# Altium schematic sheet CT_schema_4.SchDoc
size 284 x 147 mm
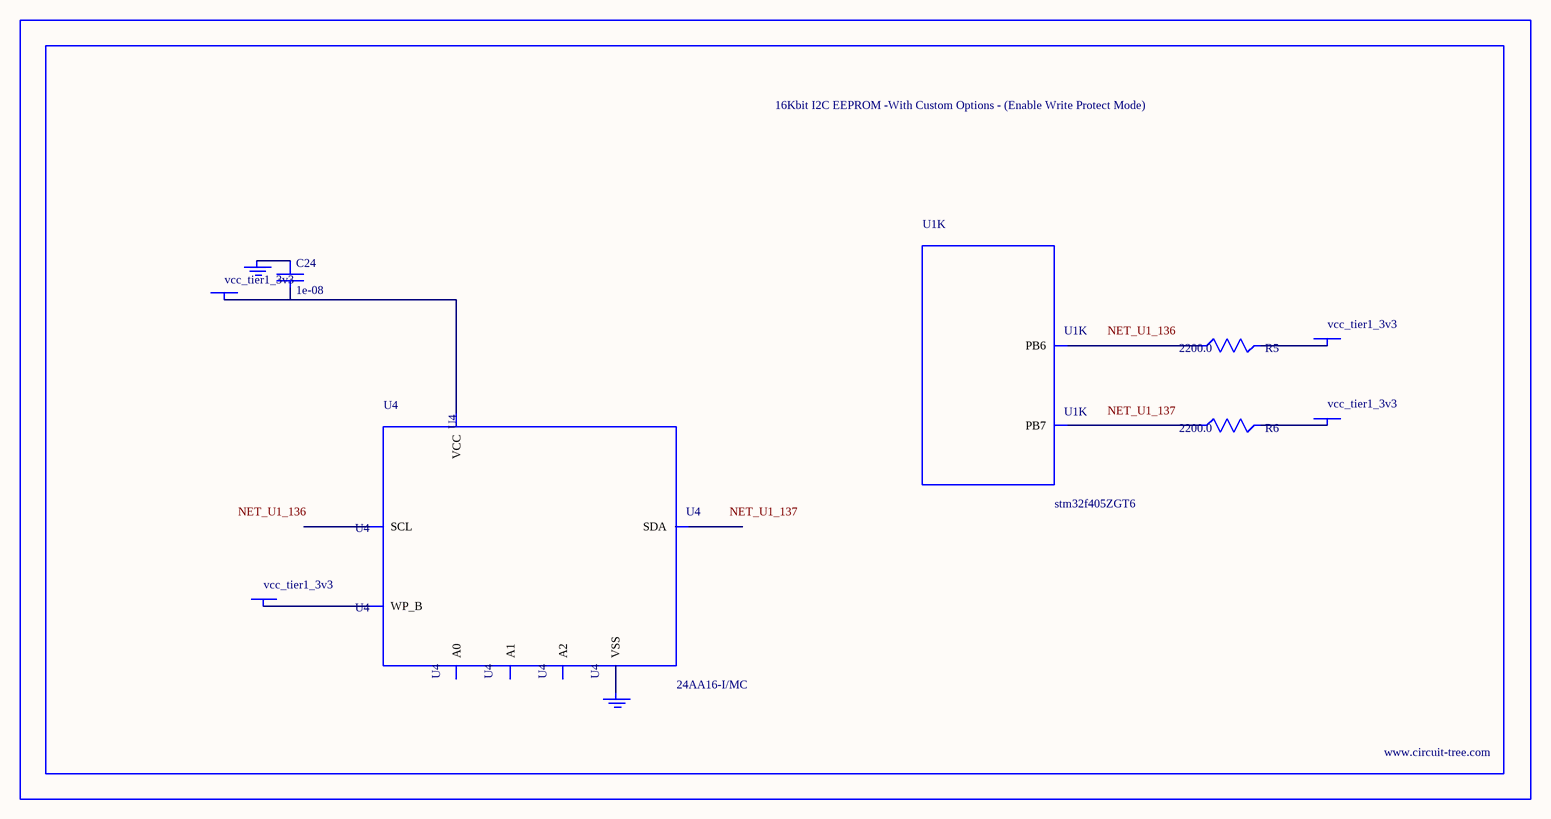
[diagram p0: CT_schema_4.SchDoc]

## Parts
BORDER3  (no value)
C24  1e-08  [C0402]
GND_INSTANCE_3_0  (no value)
GND_INSTANCE_3_1  (no value)
POWER_INSTANCE_3_0  vcc_tier1_3v3
POWER_INSTANCE_3_1  vcc_tier1_3v3
POWER_INSTANCE_3_2  vcc_tier1_3v3
POWER_INSTANCE_3_3  vcc_tier1_3v3
R5  2200.0  [R0603]
R6  2200.0  [R0603]
U1  stm32f405ZGT6  [LQFP144]  (part K of 13)
U4  24AA16-I/MC  [TDFN-8/6MM]

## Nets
NetC24_1: C24.1 GND_INSTANCE_3_0.0(GND)
NetC24_2: C24.2 POWER_INSTANCE_3_1.0(PWR) U4.8(VCC)
NetGND_INSTANCE_3_1_0: GND_INSTANCE_3_1.0(GND) U4.4(VSS)
NetPOWER_INSTANCE_3_0_0: POWER_INSTANCE_3_0.0(PWR) U4.7(WP_B)
NetPOWER_INSTANCE_3_2_0: POWER_INSTANCE_3_2.0(PWR) R5.2
NetPOWER_INSTANCE_3_3_0: POWER_INSTANCE_3_3.0(PWR) R6.2
NetR5_1: R5.1 U1.136(PB6)
NetR6_1: R6.1 U1.137(PB7)

Not connected (* = marked no-connect by the designer): U4 1(A0) 2(A1) 3(A2) 5(SDA) 6(SCL)

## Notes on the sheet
- Labels drawn without touching a wire or pin: NET_U1_136, NET_U1_137

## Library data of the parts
BORDER3 = BORDER_PAGE3
C24 = C0402C103K3RAC
GND_INSTANCE_3_0 GND_INSTANCE_3_1 = GND
POWER_INSTANCE_3_0-POWER_INSTANCE_3_3 = PWR
R5 R6 = RC0603JR-072K2L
